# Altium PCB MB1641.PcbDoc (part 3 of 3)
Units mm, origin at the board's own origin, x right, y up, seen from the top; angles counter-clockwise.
Board outline 70 x 64.48 mm, 4 copper layers (Top Layer, GND, VCC, Bottom Layer), stack 1.502 mm thick; 161 components, 126 nets, 622 pads, 1092 vias.
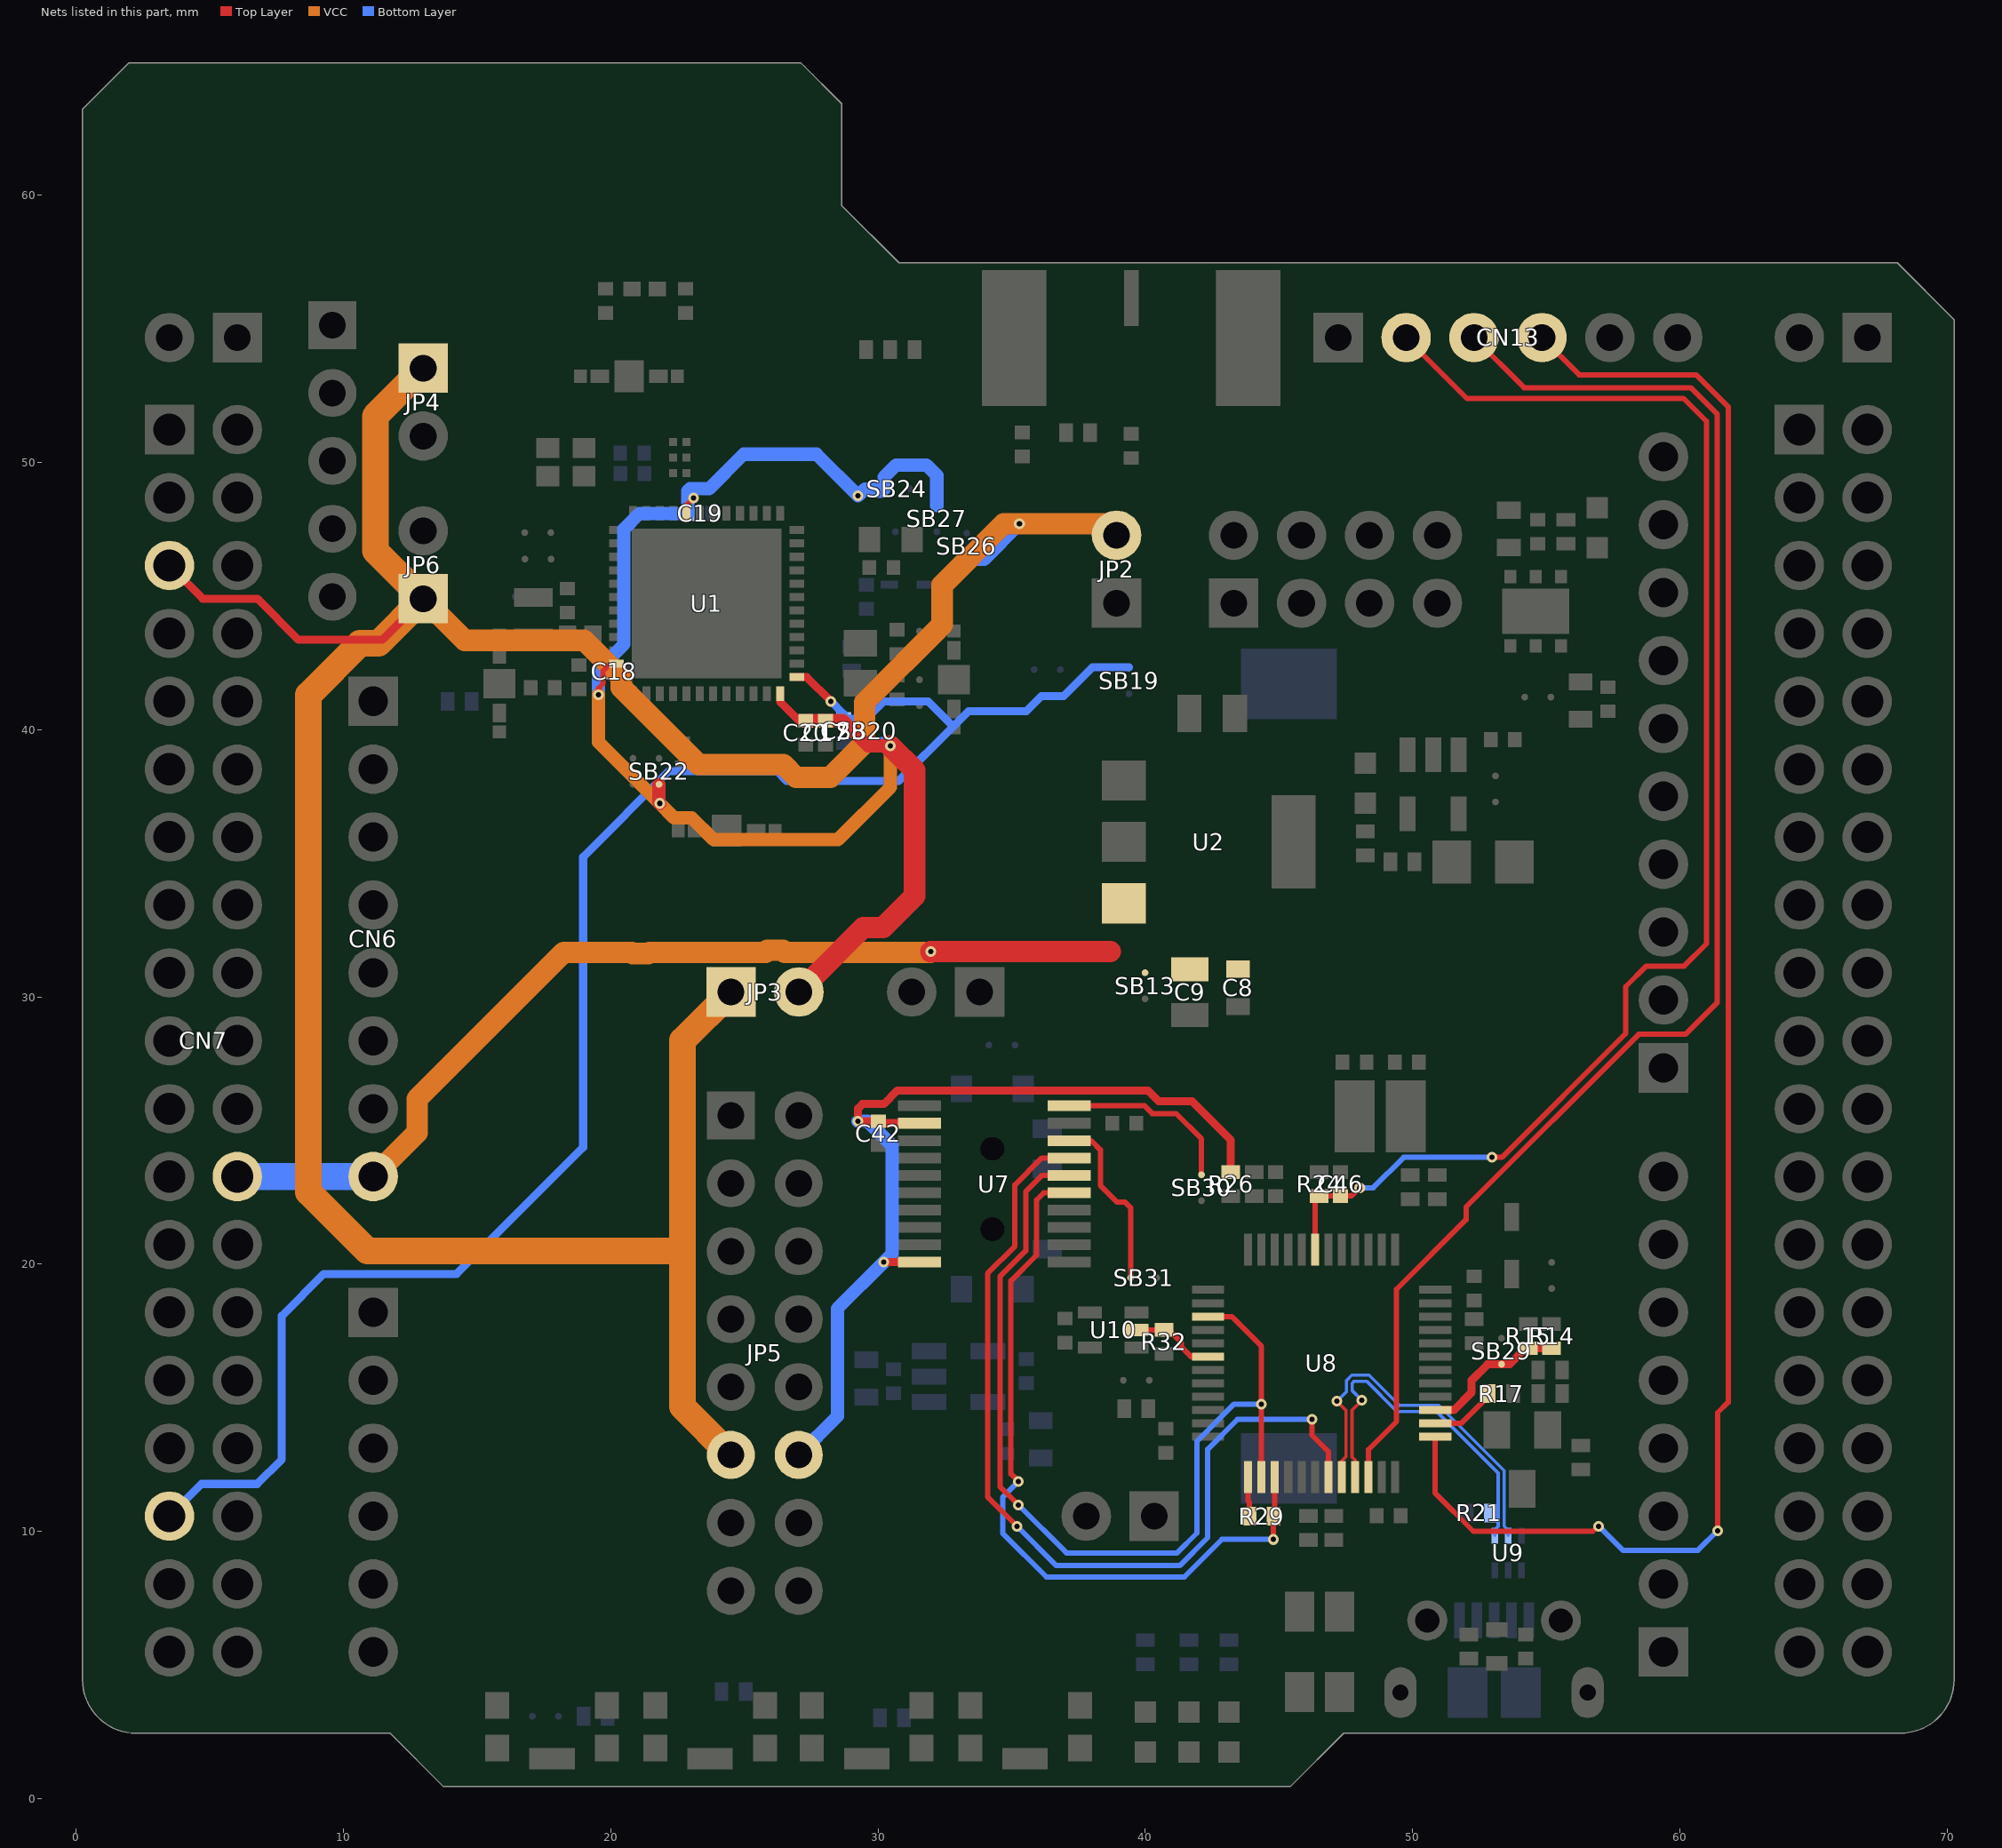
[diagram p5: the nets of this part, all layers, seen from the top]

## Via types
v1: diameter 0.4, hole 0.2, Top Layer to Bottom Layer, tented both sides, 1003 vias
v2: diameter 0.4/0.4/0.3/0.4 (per signal layer), hole 0.2, Top Layer to Bottom Layer, tented both sides, 89 vias

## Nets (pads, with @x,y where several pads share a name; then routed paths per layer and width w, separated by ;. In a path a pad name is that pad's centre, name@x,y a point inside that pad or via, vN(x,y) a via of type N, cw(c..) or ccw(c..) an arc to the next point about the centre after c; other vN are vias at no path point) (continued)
PWR_EXT: R14.2 R15.1 SB29.2 U8.39 | length 5.6
  Top Layer w0.3: U8.39@50.845,14.544 51.54,14.544 52.2,15.204 52.2,15.66 52.799,16.259 SB29.2@53.323,16.259 53.622,16.259 54.222,16.859 R15.1@54.326,16.859 R14.2@55.198,16.859
STLK_RST: C46.2 CN13.2 R24.1 U8.7 | length 53.6
  Top Layer w0.2: U8.7@46.345,20.544 46.345,22.395 R24.1@46.5,22.55 C46.2@47.3,22.55 47.708,22.55 v1(48.02,22.862) ; CN13.2@49.754,54.664 52.031,52.387 60.134,52.387 60.99,51.53 60.99,31.99 60.155,31.155 58.735,31.155 57.965,30.385 57.965,28.628 53.337,24 v1(52.96,24)
  Bottom Layer w0.2: v1(48.02,22.862) 48.521,22.862 49.659,24 v1(52.96,24)
STLK_RX: SB31.1 U7.18 | length 6.7
  Top Layer w0.2: U7.18@37.152,24.625 37.975,24.625 38.319,24.281 38.319,22.947 38.933,22.333 39.233,22.333 39.45,22.116 SB31.1@39.45,19.494
STLK_SWCLK: CN13.4 U8.37 | length 64.2
  Top Layer w0.2: U8.37@50.845,13.544 50.845,11.433 52.265,10.013 56.735,10.013 v1@56.924,10.201 ; CN13.4@54.834,54.664 56.224,53.274 60.601,53.274 61.797,52.078 61.797,14.839 61.406,14.448 v1(61.406,10.034)
  Bottom Layer w0.2: v1(56.957,10.201) 57.858,9.3 60.672,9.3 v1(61.406,10.034)
STLK_SWDIO: CN13.3 U8.34 | length 56.5
  Top Layer w0.2: U8.34@48.345,12.044 48.345,13.064 49.392,14.111 49.392,19.067 51.994,21.669 51.994,22.144 58.45,28.6 60.2,28.6 61.394,29.794 61.394,51.796 60.4,52.79 54.168,52.79 CN13.3@52.294,54.664
STLK_TX: SB30.1 U7.20 | length 6.8
  Top Layer w0.2: U7.20@37.152,25.925 39.975,25.925 40.26,25.64 41.15,25.64 42.1,24.69 SB30.1@42.1,23.35
T_NRST: R32.1 U8.18 U10.2 | length 3.2
  Top Layer w0.2: U10.2@39.675,17.54 40.69,17.54 R32.1@40.7,17.55 40.87,17.55 41.34,17.08 41.34,16.91 41.706,16.544 U8.18@42.345,16.544
T_SWCLK: U7.16 U8.15 U8.26 | length 35.8
  Top Layer w0.2: v1@35.254,10.995 v1(35.249,11) 34.567,11.682 34.567,19.544 35.527,20.504 35.527,22.719 36.133,23.325 U7.16@37.152,23.325 ; U8.15@42.345,18.044 43.229,18.044 44.345,16.929 v1(44.345,14.767) U8.26@44.345,12.044
  Bottom Layer w0.2: v1(35.249,11) 37.049,9.2 41.186,9.2 41.931,9.945 41.931,13.378 43.32,14.767 v1(44.345,14.767)
T_SWDIO: R29.1 U7.15 U8.27 | length 28.3
  Top Layer w0.2: v1(35.254,11.875) 34.97,12.159 34.97,19.377 35.93,20.337 35.93,22.4 36.205,22.675 U7.15@37.152,22.675 ; v1(44.795,9.705) R29.1@44.795,10.576 44.845,10.626 U8.27@44.845,12.044
  Bottom Layer w0.2: v1(35.254,11.875) 34.673,11.294 34.673,9.927 36.3,8.3 41.457,8.3 42.862,9.705 v1(44.795,9.705)
T_SWDIO_IN: R29.2 U8.25 | length 1.5
  Top Layer w0.2: U8.25@43.845,12.044 43.845,11.155 43.895,11.105 R29.2@43.895,10.576
T_SWO: U7.17 U8.31 | length 34.3
  Top Layer w0.2: v1(35.2,10.2) 34.1,11.3 34.1,19.654 35.119,20.673 35.119,22.965 36.129,23.975 U7.17@37.152,23.975 ; v1(46.227,14.2) 46.227,13.618 46.845,13 U8.31@46.845,12.044
  Bottom Layer w0.2: v1(35.2,10.2) 36.67,8.73 41.286,8.73 42.334,9.778 42.334,13.083 43.451,14.2 v1(46.227,14.2)
T_VDD: C42.2 JP5.12 R26.1 U7.2 U7.10 | length 35
  Top Layer w0.3: v1(30.212,20.075) U7.10@31.552,20.075 ; U7.2@31.552,25.275 30.087,25.275 C42.2@30.012,25.35 v1(29.256,25.35) 29.256,25.823 29.425,25.992 30.219,25.992 30.726,26.5 40.1,26.5 40.5,26.1 41.74,26.1 43.2,24.64 R26.1@43.2,23.45
  Bottom Layer w0.5: JP5.12@27.037,12.867 28.48,14.31 28.48,18.342 v1(30.212,20.075) 30.528,20.39 30.528,24.434 29.612,25.35 v1(29.256,25.35)
USB_RENUMn: R17.1 U8.38 | length 2.5
  Top Layer w0.2: U8.38@50.845,14.044 51.804,14.044 52.85,15.09 R17.1@52.85,15.159
USBSTLK_N: U8.32 U9.2 | length 13.9
  Top Layer w0.12: v1(47.165,14.873) 47.5,14.539 47.5,12.8 47.345,12.645 U8.32@47.345,12.044
  Bottom Layer w0.12: v1(47.165,14.873) 47.522,15.23 47.522,15.648 47.721,15.848 48.367,15.848 49.496,14.718 50.981,14.718 53.418,12.281 53.418,10.203 53.574,10.047 U9.2@53.574,9.85
USBSTLK_P: R21.1 U8.33 U9.1 | length 13.2
  Top Layer w0.12: U8.33@47.845,12.044 47.845,12.675 47.731,12.789 47.731,14.54 v1(48.1,14.909)
  Bottom Layer w0.12: v1(48.1,14.909) 47.744,15.265 47.744,15.556 47.813,15.626 48.275,15.626 49.404,14.496 50.889,14.496 53.196,12.189 53.196,10.194 53.074,10.072 U9.1@53.074,9.85
VBAT: C28.1 CN7.33 SB19.2 SB20.2 U1.1 | length 66.1
  Top Layer w0.3: U1.1@26.964,41.962 27.338,41.962 v1(28.239,41.061)
  Bottom Layer w0.3: CN7.33@3.5,10.58 4.702,11.782 6.782,11.782 7.7,12.7 7.7,18.069 9.271,19.64 14.24,19.64 18.974,24.374 18.974,35.233 22.188,38.447 26.211,38.447 26.58,38.078 30.777,38.078 32.817,40.118 ; v1(28.239,41.061) 28.718,40.582 C28.1@28.718,40.403 29.562,40.403 SB20.2@29.6,40.441 30.22,41.061 31.875,41.061 32.817,40.118 ; SB19.2@39.39,42.328 38.02,42.328 36.946,41.253 36.117,41.253 35.546,40.682 33.381,40.682 32.817,40.118
VDD: CN7.5 JP2.2 JP3.1 JP4.1 JP5.11 JP6.1 SB26.2 | length 116.8
  Top Layer w0.3: CN7.5@3.5,46.14 4.746,44.894 6.792,44.894 8.324,43.362 11.46,43.362 JP6.1@12.992,44.894
  VCC w0.8: JP6.1@12.992,44.894 14.548,43.339 19.011,43.339 20.387,41.963 20.387,41.907 20.403,41.891 20.403,41.575 23.278,38.7 26.457,38.7 26.943,38.214 28.214,38.214 29.5,39.5 29.5,41.017 32.4,43.917 32.4,45.4 34.7,47.7 v1(35.292,47.7) 38.495,47.7 JP2.2@38.925,47.27
  VCC w1: JP4.1@12.992,53.519 11.2,51.727 11.2,46.687 JP6.1@12.992,44.894 11.327,43.229 10.629,43.229 8.7,41.3 8.7,22.7 10.9,20.5 22.687,20.5 ; JP5.11@24.497,12.867 22.687,14.677 22.687,20.5 ; JP3.1@24.503,30.183 22.687,28.367 22.687,20.5
  Bottom Layer w0.5: SB26.2@33.32,46.375 33.967,46.375 v1(35.292,47.7)
VDD_MCU: C17.2 C18.2 C19.2 C20.2 JP3.2 SB20.1 SB22.1 SB24.1 SB27.2 U1.20 U1.35 U1.48 | length 60.2
  Top Layer w0.2: v1(19.55,41.3) 19.55,41.546 19.713,41.709 19.713,42.195 19.98,42.462 U1.35@20.214,42.462 U1.35@20.195,42.443 ; U1.20@22.839,48.087 22.839,48.407 v1(23.099,48.666)
  Top Layer w0.3: U1.48@26.339,41.337 26.339,41.045 27.049,40.335 C20.2@27.3,40.335
  Top Layer w0.5: SB22.1@21.81,37.95 21.81,37.268 v1(21.839,37.239) ; C20.2@27.3,40.335 C17.2@28.042,40.335 28.688,40.335 29.639,39.384 v1(30.469,39.384)
  Top Layer w0.8: JP3.2@27.043,30.183 29.45,32.59 30.19,32.59 31.37,33.77 31.37,38.483 v1(30.469,39.384)
  VCC w0.5: v1@19.55,41.319 v1(19.55,41.3) 19.55,39.53 19.549,39.529 v1(21.839,37.239) 22.375,36.703 23.03,36.703 23.85,35.883 28.503,35.883 30.469,37.849 v1(30.469,39.384)
  Bottom Layer w0.5: v1@19.55,41.319 19.55,42.299 19.608,42.299 20.5,43.191 20.5,47.5 21.087,48.087 C19.2@22.889,48.087 22.889,48.933 22.963,49.008 23.683,49.008 24.975,50.3 27.7,50.3 v1(29.256,48.744) 29.512,49 29.893,49 29.98,48.913 30.138,48.913 SB24.1@30.225,49 30.225,49.445 30.68,49.9 31.807,49.9 32.2,49.507 SB27.2@32.2,48.375 ; SB20.1@29.682,39.384 SB20.1@29.6,39.466 30.387,39.466 v1(30.469,39.384)
VIN: C8.2 C9.1 CN6.8 CN7.24 SB13.2 U2.3 | length 36.9
  Top Layer w0.8: v1(31.97,31.69) 31.98,31.7 38.689,31.7
  VCC w0.8: CN6.8@11.12,23.28 12.76,24.92 12.76,26.18 18.251,31.671 20.786,31.671 20.833,31.624 21.413,31.624 21.46,31.671 25.79,31.671 25.86,31.741 26.44,31.741 26.51,31.671 v1@31.951,31.671
  Bottom Layer w1: CN7.24@6.04,23.28 CN6.8@11.12,23.28
pads on no net: B1.5 B2.5 B3.5 B4.5 CN6.1 CN7.1 CN7.2 CN7.3 CN7.4 CN7.9 CN7.11 CN7.17 CN7.21 CN7.22 CN7.23 CN7.26 CN7.29 CN7.31 CN7.35 CN7.37 CN10.1 CN10.2 CN10.4 CN10.6 CN10.10 CN10.16 CN10.18 CN10.22 CN10.24 CN10.26 CN10.28 CN10.34 CN10.36 CN10.38 CN13.5 SW5.NPTH1 SW5.NPTH2 U3.3 U3.5 U7.7 U7.8 U7.9 U8.4 U8.11 U8.14 U8.16 U8.17 U8.19 U8.22 U8.29 U8.40 U8.41 U8.42 U8.43 U8.45 U8.46 U9.4 U10.1

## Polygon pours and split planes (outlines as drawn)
GND on Top Layer "Top Layer-GND" (solid, remove dead copper, pour order 42): -0.442,57.548 1.658,57.548 70.937,57.548 75.758,52.727 75.858,52.627 75.858,9.707 75.858,3.807 69.058,-2.993 66.458,-5.593 33.958,-5.593 0.458,-5.593 -5.042,-0.093 -8.842,3.707 -8.842,37.501 -8.842,53.107 -4.442,57.507
GND on Top Layer "Top Layer-GND" (solid, remove dead copper, pour order 20): 45.512,57.494 45.512,57.46 45.512,51.409 45.512,50.895 44.162,49.545 43.895,49.278 37.432,49.278 31.864,49.278 30.075,51.067 25.009,51.067 24.69,51.067 23.551,49.928 23.551,49.15 23.154,48.753 23.154,47.333 21.274,47.333 21.242,48.698 20.662,49.278 20.751,49.367 20.751,50.956 20.751,52.442 18.94,54.253 18.662,54.532 18.662,56.653 18.662,57.172 18.984,57.494 37.056,57.494
VIN on Top Layer "Top Layer-VIN" (solid, remove dead copper, pour order 18): 39.364,34.251 40.225,34.251 42.549,34.251 44.1,32.7 44.1,31.2 44.1,30.821 43.9,30.621 43.879,30.6 42,30.6 38.214,30.6 37.9,30.914 37.7,31.114 37.7,31.4 37.7,32.636 39.119,34.251
3V3 on Top Layer "Top Layer-3V3" (solid, remove dead copper, pour order 24): 55.3,46.2 56.957,46.2 57.376,46.2 57.596,45.98 57.8,45.776 57.8,45.289 57.8,41.409 57.7,41.309 57.66,41.269 57.3,41.269 56.184,41.269 55.9,40.985 55.7,40.785 55.7,40.641 55.7,39.38 55.93,39.15 56.007,39.073 56.3,39.073 56.42,39.073 56.65,38.843 56.7,38.793 56.7,38.022 56.7,37.893 56.58,37.773 56.549,37.742 56.224,37.742 55.108,37.742 54.95,37.9 54.912,37.938 54.912,38.3 54.912,42.432 55.124,42.644 55.148,42.668 55.659,42.668 55.939,42.668 56.15,42.88 56.15,43.15 56.15,45.269 56.08,45.339 55.957,45.462 55.59,45.462 55.308,45.462 55.213,45.557 55.213,46.1 55.213,46.134 55.279,46.2
GND on Top Layer "Top Layer-GND" (solid, remove dead copper, pour order 16): 38.417,37.3 39.125,37.3 41.168,37.3 41.97,38.102 42.074,38.206 42.074,40.491 42.074,41.236 41.957,41.353 38.891,41.353 38.311,40.773 38.311,37.406
5V_INT on Top Layer "Top Layer-5V_INT" (solid, remove dead copper, pour order 14): 38.4,34.748 41.631,34.748 43.076,34.748 43.9,33.923 44.185,33.639 45.6,33.639 46.325,33.639 46.67,33.984 46.845,34.159 46.845,35.662 46.845,41.403 46.157,42.091 45.5,42.091 43.175,42.091 42.85,41.766 42.745,41.661 42.745,40.9 42.745,37.375 42.174,36.8 42.074,36.7 39.862,36.7 38.4,36.7 38.2,36.5 38.2,36.098 38.2,34.859 38.311,34.748
5V_USB_STLINK on Top Layer "Top Layer-5V_USB_STLINK" (solid, remove dead copper, pour order 12): 53.446,37.529 52.8,37.529 51.287,37.529 51.258,37.5 51.2,37.442 51.2,36.9 51.2,36.4 50.7,35.9 50.3,35.5 50.12,35.5 49.854,35.5 49.754,35.4 49.754,35.048 49.754,34.409 49.545,34.2 49,34.2 48.7,34.2 48.6,34.3 48.6,34.7 48.6,35.524 48.524,35.6 48.181,35.6 47.831,35.6 47.731,35.5 47.731,34.748 47.731,32.617 48.314,32.034 51.679,32.034 52.2,32.555 52.2,34.2 52.2,35.725 52.475,36 53.15,36 53.356,36 53.554,36.198 53.65,36.294 53.65,36.8 53.65,37.479 53.6,37.529
NetC12_2 on Top Layer "Top Layer-NetC12_2" (solid, remove dead copper, pour order 10): 51.4,38.343 51.409,38.334 52.193,38.334 52.468,38.334 52.654,38.148 52.7,38.102 52.7,37.954 52.746,37.9 53.096,37.9 53.5,37.9 53.6,38 53.622,38.022 53.622,38.442 53.622,38.682 53.4,38.904 53.3,39.004 53.3,39.629 53.3,41.9 53.133,42.068 51.676,42.076 51.4,41.8
5V on Top Layer "Top Layer-5V" (solid, remove dead copper, pour order 6): 53.97,43.316 53.97,42.947 53.97,42.87 53.8,42.7 53.52,42.42 52.524,42.42 52.3,42.644 52.3,43.854 52.3,46.946 52.624,47.27 52.654,47.3 54.402,47.3 56,47.3 56.1,47.2 56.15,47.15 56.15,46.962 56.15,46.72 56.03,46.6 55.93,46.5 55.213,46.5 54.3,46.5 54,46.2 53.925,46.125 53.925,45.73 53.925,45.557 53.868,45.5 53.83,45.462 53.671,45.462 53.321,45.462 53.259,45.4 53.182,45.324 53.182,44.4 53.182,43.517 53.259,43.441 53.3,43.4 53.671,43.4 53.935,43.4 53.944,43.391
ANT on Top Layer "Top Layer-ANT" (solid, pour order 0): 20.021,57.65 20.021,59.275 17.546,59.275 17.546,60 26.471,60 26.471,61.65 17.546,61.65 17.546,62.375 26.496,62.375 26.496,64.05 19.521,64.05 19.521,63.6 23.921,63.6 26.021,63.6 26.021,62.85 17.096,62.85 17.096,62.8 17.096,61.175 17.121,61.175 25.996,61.175 25.996,60.8 25.996,60.425 25.921,60.425 17.096,60.425 17.096,60.4 17.096,58.775 17.121,58.775 19.621,58.775 19.621,57.625 20.021,57.625
GND on Bottom Layer "Bottom Layer-GND" (solid, remove dead copper, pour order 44): 1.448,57.511 3.548,57.511 72.827,57.511 77.648,52.69 77.748,52.59 77.748,9.67 77.748,3.77 70.948,-3.03 68.348,-5.63 35.848,-5.63 2.348,-5.63 -3.152,-0.13 -6.952,3.67 -6.952,37.464 -6.952,53.07 -2.552,57.47
5V_USB_STLINK on Bottom Layer "Bottom Layer-5V_USB_STLINK" (solid, remove dead copper, pour order 40): 29.08,15.3 29.08,13.862 29.292,13.65 32.771,13.65 33.177,14.056 33.177,16.872 32.851,17.199 31.299,17.199 31.162,17.062 31.162,16.504 31.216,16.45 32.568,16.45 32.668,16.35 32.668,15.387 32.531,15.25 31.013,15.25 30.856,15.407 29.138,15.407 29.094,15.363
3V3_STLINK on Bottom Layer "Bottom Layer-3V3_STLINK" (solid, remove dead copper, pour order 2): 34.315,15.159 33.54,15.159 33.46,15.079 33.46,13.782 33.642,13.6 36.757,13.6 37,13.357 37,12.92 37.32,12.6 40.19,12.6 40.3,12.71 40.3,14.129 39.62,14.809 36.6,14.809 35.358,14.809 35.008,15.159
GND on VCC "VCC" (solid, remove dead copper, pour order 28): -0.2,57.541 1.9,57.541 71.179,57.541 76,52.72 76.1,52.62 76.1,9.7 76.1,3.8 69.3,-3 66.7,-5.6 34.2,-5.6 0.7,-5.6 -4.8,-0.1 -8.6,3.7 -8.6,37.494 -8.6,53.1 -4.2,57.5
GND on GND "GND" (solid, remove dead copper, pour order 38): -0.2,57.541 1.9,57.541 71.179,57.541 76,52.72 76.1,52.62 76.1,9.7 76.1,3.8 69.3,-3 66.7,-5.6 34.2,-5.6 0.7,-5.6 -4.8,-0.1 -8.6,3.7 -8.6,37.494 -8.6,53.1 -4.2,57.5

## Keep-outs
Top Layer:
  rectangle: 29.997,53.902 30.053,54.538
  rectangle: 30.887,53.924 30.925,54.563
  rectangle: 37.475,50.774 37.5,51.456
GND:
  lines w0.05: 22.151,49.767 22.504,49.767 22.504,47.806 22.154,47.806 22.151,49.767
Keep-Out Layer:
  lines w0.1: 0.25,57.46 0.25,4.46 ccw(c2.25,4.46) 2.25,2.46 11.75,2.46 13.751,0.459 45.423,0.459 47.424,2.46 68.25,2.46 ; 0.25,57.46 0.25,57.46 ; 0.25,57.46 0.25,63.21 1.976,64.936 27.122,64.936 28.646,63.412 28.646,59.602 30.788,57.46 68.126,57.46 70.25,55.336 70.25,4.46 cw(c68.25,4.46) 68.25,2.46 ; 68.25,2.46 68.25,2.46 ; 3.52,2.663 3.52,3.918 6.475,3.918 6.475,2.663 3.52,2.663
  lines w0.102: 13.731,0.444 ccw(c13.766,0.48) 13.777,0.43 ccw(c13.779,0.481) 13.779,0.43 ; 45.417,0.43 ccw(c45.451,0.467) 45.487,0.431
  lines w0.127: 0.25,4.46 ccw(c2.25,4.46) 2.25,2.46 ; 68.25,2.46 ccw(c68.25,4.46) 70.25,4.46

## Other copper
Top Layer:
  text "1" at 3.886,3.041 h0.51
GND:
  text "2" at 4.446,3.04 h0.51
VCC:
  text "3" at 5.146,3.03 h0.51
Bottom Layer:
  text "4" at 5.78,3.033 h0.51

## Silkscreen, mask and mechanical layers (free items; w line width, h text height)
Top Overlay:
  rectangle: 56.493,52.405 58.55,53.109
  lines w0.1: 0.546,57.541 30.62,57.541
  lines w0.12: 28.467,11.4 30.087,11.4 ; 29.952,31.483 29.952,32.767 ; 35.079,32.767 29.952,32.767 ; 35.112,31.483 35.112,32.767 ; 35.112,32.752 35.112,35.65 29.952,35.65 29.952,32.767 ; 36.48,9.3 36.48,6.824 41.64,6.824 41.64,9.3 ; 42.033,48.54 42.033,51.346 52.18,51.346 ; 42.033,50.365 52.188,50.365 ; 52.188,48.55 52.188,51.346
  lines w0.15: 51.994,13.19 51.994,15.603 52.693,16.302
  lines w0.2: 23.09,6.415 19.17,6.415 19.17,27.037 23.09,27.037 ; 28.467,6.415 30.087,6.415 30.087,14.81 ; 28.573,14.81 30.082,14.81
  text "J" at 2.17,57.49 h15.24
  text "STLINK (Reserved)" at 50,56.444 h0.6
  text "GND" at 63.88,56.444 h0.51
  text "GND" at 66.57,56.404 h0.51
  text "GND" at 2.957,56.21 h0.51
  text "GND" at 5.64,56.21 h0.51
  text "VDD" at 15.13,53.109 h0.51 r90
  text "SWDIO" at 51.289,52.5 h0.51
  text "SWCLK" at 53.941,52.5 h0.51
  text "Vref" at 59.5,52.5 h0.51
  text "GND" at 46.475,52.48 h0.51
  text "NRST" at 48.966,52.49 h0.51
  text "2" at 68.825,51.153 h0.51
  text "1" at 62.65,51.1 h0.51
  text "1" at 1.495,51.055 h0.51
  text "5V sources" at 44.7,50.57 h0.6
  text "D15" at 61.948,50.091 h1 r90
  text "VDDRF" at 15.24,49.93 h0.51 r90
  text "5V / VIN" at 46.729,48.724 h0.51 r90
  text "5V / EXT" at 44.27,48.689 h0.51 r90
  text "USB / STL" at 51.801,48.689 h0.51 r90
  text "USB / MCU" at 49.3,48.68 h0.51 r90
  text "3" at 1.384,48.562 h0.51
  text "4" at 68.825,48.512 h0.51
  text "3" at 62.624,48.354 h0.51
  text "D14" at 62,47.27 h1 r90
  text "VDD" at 37,46.9 h0.51 r90
  text "VDDSMPS" at 15.25,46.15 h0.51 r90
  text "6" at 68.825,45.895 h0.51
  text "5" at 1.384,45.87 h0.51
  text "5" at 62.624,45.661 h0.51
  text "VDD" at 15.221,44.17 h0.51 r90
  text "3V3" at 36.94,44.047 h0.51 r90
  text "8" at 68.825,43.381 h0.51
  text "7" at 1.384,43.228 h0.51
  text "AVDD" at 61.907,43.117 h1 r90
  text "7" at 62.624,43.02 h0.51
  text "8" at 7.569,42.562 h0.51
  text "GND" at 57.759,42.324 h1 r90
  text "10" at 68.825,40.866 h0.51
  text "9" at 1.409,40.841 h0.51
  text "10" at 7.598,40.669 h0.51
  text "9" at 62.648,40.632 h0.51
  text "D13" at 55.566,38.42 h1
  text "12" at 68.825,38.326 h0.51
  text "11" at 1.23,38.25 h0.51
  text "12" at 7.655,38.144 h0.51
  text "11" at 62.469,38.041 h0.51
  text "D12" at 55.623,36.77 h1
  text "IOREF" at 13.918,36.4 h1 r90
  text "13" at 1.012,35.71 h0.51
  text "14" at 68.825,35.71 h0.51
  text "14" at 7.54,35.649 h0.51
  text "13" at 62.251,35.501 h0.51
  text "NRST" at 12.8,34.77 h1
  text "D11" at 55.82,34.64 h1
  text "RF Part" at 24.356,34.621 h1
  text "15" at 1.012,33.246 h0.51
  text "16" at 68.825,33.17 h0.51
  text "16" at 7.54,33.153 h0.51
  text "15" at 62.251,33.038 h0.51
  text "3V3" at 12.83,32.85 h1
  text "Ext Battery" at 30.597,32.85 h0.75
  text "D10" at 55.623,32.106 h1
  text "-" at 30.62,31.74 h1
  text "+" at 33.351,31.72 h1
  text "18" at 68.825,30.655 h0.51
  text "17" at 1.012,30.605 h0.51
  text "18" at 7.511,30.515 h0.51
  text "17" at 62.251,30.396 h0.51
  text "5V" at 12.91,30.21 h1
  text "D9" at 55.98,29.327 h1
  text "K" at 15.316,28.702 h13
  text "20" at 68.825,28.369 h0.51
  text "19" at 1.036,28.166 h0.51
  text "20" at 7.569,28.105 h0.51
  text "VDD" at 23.012,27.963 h0.51
  text "19" at 62.275,27.958 h0.51
  text "VDD_MCU" at 25.54,27.926 h0.51
  text "GND" at 12.772,27.8 h1
  text "D8" at 56.08,26.788 h1
  text "22" at 68.825,25.728 h0.51
  text "21" at 1.15,25.626 h0.51
  text "21" at 62.125,25.624 h0.51
  text "22" at 7.615,25.613 h0.51
  text "GND" at 12.8,25.35 h1
  text "GND" at 20.792,25.335 h0.75
  text "24" at 68.825,23.061 h0.51
  text "23" at 0.932,22.985 h0.51
  text "23" at 61.907,22.982 h0.51
  text "24" at 7.626,22.913 h0.51
  text "D7" at 56.375,22.847 h1
  text "NRST" at 20.219,22.759 h0.75
  text "VIN" at 12.872,22.4 h1
  text "25" at 0.932,20.546 h0.51
  text "25" at 61.907,20.544 h0.51
  text "26" at 68.825,20.445 h0.51
  text "D6" at 56.347,20.337 h1
  text "26" at 7.626,20.303 h0.51
  text "SWDIO" at 19.837,20.277 h0.75
  text "27" at 0.932,18.108 h0.51
  text "27" at 61.907,18.105 h0.51
  text "28" at 68.825,18.057 h0.51
  text "28" at 7.655,17.836 h0.51
  text "SWCLK" at 19.456,17.639 h0.75
  text "D5" at 56.3,17.569 h1
  text "A0" at 12.807,17.48 h1
  text "30" at 68.825,15.492 h0.51
  text "30" at 7.598,15.456 h0.51
  text "29" at 0.956,15.39 h0.51
  text "29" at 61.932,15.387 h0.51
  text "D4" at 56.347,15.363 h1
  text "SWO" at 20.537,15.22 h0.75
  text "A1" at 12.888,14.976 h1
  text "D3" at 56.3,13.8 h1
  text "32" at 68.825,12.926 h0.51
  text "31" at 1.15,12.875 h0.51
  text "31" at 62.125,12.873 h0.51
  text "32" at 7.626,12.817 h0.51
  text "A2" at 12.868,12.581 h1
  text "VDD / MCU" at 20.41,11.88 h0.75
  text "T_VDD" at 29.579,11.6 h0.7 r90
  text "34" at 68.825,10.386 h0.51
  text "33" at 0.932,10.361 h0.51
  text "33" at 61.907,10.358 h0.51
  text "34" at 7.626,10.321 h0.51
  text "D2" at 56.347,10.201 h1
  text "MB1641C" at 18.161,10.16 h2.5 r90
  text "A3" at 12.807,9.969 h1
  text "TX" at 21.428,9.971 h0.75
  text "RX" at 29.748,9.398 h0.75 r90
  text "L" at 30.85,8.88 h7.62
  text "TX" at 37.2,8.24 h0.75
  text "RX" at 39.8,8.24 h0.75
  text "36" at 68.825,7.872 h0.51
  text "35" at 0.932,7.745 h0.51
  text "35" at 61.907,7.742 h0.51
  text "36" at 7.655,7.711 h0.51
  text "D1" at 56.545,7.5 h1
  text "A4" at 12.807,7.465 h1
  text "RX" at 21.46,7.394 h0.75
  text "STLINK" at 37.6,7.1 h0.75
  text "TX" at 29.748,6.866 h0.75 r90
  text "Reset" at 32.7,5.97 h1
  text "COM" at 44.75,5.63 h0.75 r90
  text "38" at 68.825,5.205 h0.51
  text "37" at 0.932,5.179 h0.51
  text "D0" at 56.357,5.15 h1
  text "38" at 7.583,5.083 h0.51
  text "A5" at 12.807,4.961 h1
  text "37" at 62.14,4.1 h0.51
  text "TOP SILKSCREEN" at -0.752,-18.74 h1.52
Bottom Overlay:
  lines w0.1: 7.5,51.79 7.5,55.39 8.55,55.39 ; 7.51,46.66 7.51,48.35 ; 7.51,49.1 7.51,50.92 ; 7.531,44.01 7.531,45.81 ; 7.73,43.3 11.71,43.3 11.71,55.55 ; 29.743,24.615 29.743,24.557 29.753,24.547 29.806,24.547 29.855,24.498 29.723,24.498 29.679,24.542 29.679,24.539 29.592,24.452 29.93,24.452 29.989,24.393 29.528,24.393 29.472,24.337 30.05,24.337 30.108,24.279 29.426,24.279 29.367,24.22 30.133,24.22 30.208,24.145 29.265,24.145 29.187,24.067 30.311,24.067 30.406,23.972 29.094,23.972 29.166,23.9 29.168,23.9 ; 29.757,20.973 29.757,21.032 29.747,21.042 29.694,21.042 29.645,21.091 29.776,21.091 29.82,21.047 29.82,21.049 29.908,21.137 29.57,21.137 29.511,21.195 29.972,21.195 30.027,21.251 29.45,21.251 29.391,21.31 30.074,21.31 30.133,21.368 29.367,21.368 29.292,21.444 30.235,21.444 30.313,21.522 29.189,21.522 29.094,21.617 30.405,21.617 30.334,21.688 30.332,21.688 ; 32.253,26.56 28.371,26.56 28.371,19.01 32.35,19.01 ; 29.168,23.9 30.527,23.9 29.75,24.676 28.974,23.9 29.168,23.9 ; 30.332,21.688 28.973,21.688 29.75,20.912 30.526,21.688 30.332,21.688
  text "GND" at 65.066,55.928 h0.51
  text "GND" at 67.581,55.776 h0.51
  text "AT0" at 10.84,54.01 h0.6 r270
  text "AT1" at 10.78,51.92 h0.6 r270
  text "2" at 68.857,51.179 h0.51
  text "2" at 7.5,51.13 h0.51
  text "1" at 1.845,50.975 h0.51
  text "1" at 62.897,50.848 h0.51
  text "AT2" at 10.8,49.29 h0.6 r270
  text "4" at 68.881,48.537 h0.51
  text "4" at 7.531,48.48 h0.51
  text "3" at 1.963,48.435 h0.51
  text "3" at 62.897,48.308 h0.51
  text "AT3" at 10.82,46.8 h0.6 r270
  text "E" at 57.27,46.129 h7.62
  text "6" at 7.5,46.01 h0.51
  text "6" at 68.833,45.921 h0.51
  text "5" at 1.963,45.895 h0.51
  text "5" at 62.897,45.768 h0.51
  text "GND" at 10.8,44.28 h0.6 r270
  text "Analog Test Pin (Reserved)" at 7.872,43.9 h0.6 r270
  text "8" at 68.857,43.406 h0.51
  text "7" at 1.963,43.355 h0.51
  text "8" at 7.61,43.32 h0.51
  text "7" at 62.897,43.228 h0.51
  text "10" at 69.229,40.892 h0.51
  text "9" at 1.963,40.815 h0.51
  text "10" at 8.193,40.739 h0.51
  text "9" at 62.897,40.688 h0.51
  text "12" at 69.229,38.352 h0.51
  text "G" at 58.04,38.332 h11
  text "11" at 1.963,38.275 h0.51
  text "12" at 8.193,38.199 h0.51
  text "11" at 62.897,38.148 h0.51
  text "C" at 21.62,35.95 h7.62
  text "13" at 1.963,35.735 h0.51
  text "14" at 69.253,35.735 h0.51
  text "13" at 62.897,35.608 h0.51
  text "14" at 8.217,35.583 h0.51
  text "15" at 1.963,33.195 h0.51
  text "16" at 69.205,33.195 h0.51
  text "15" at 62.897,33.068 h0.51
  text "16" at 8.169,33.043 h0.51
  text "I" at 25.95,32.707 h7.62
  text "H" at 21.46,31.93 h7.62
  text "CR2032" at 35.771,31.412 h0.9 r270
  text "18" at 69.229,30.681 h0.51
  text "17" at 1.963,30.655 h0.51
  text "18" at 8.193,30.528 h0.51
  text "17" at 62.897,30.528 h0.51
  text "20" at 69.309,28.395 h0.51
  text "20" at 8.273,28.242 h0.51
  text "19" at 1.963,28.115 h0.51
  text "19" at 62.897,27.988 h0.51
  text "22" at 69.309,25.753 h0.51
  text "22" at 8.273,25.601 h0.51
  text "21" at 1.963,25.575 h0.51
  text "21" at 62.897,25.448 h0.51
  text "Bat" at 32.131,24.948 h1
  text "24" at 69.333,23.086 h0.51
  text "23" at 1.963,23.035 h0.51
  text "24" at 8.297,22.934 h0.51
  text "23" at 62.897,22.908 h0.51
  text "25" at 1.963,20.495 h0.51
  text "26" at 69.285,20.47 h0.51
  text "25" at 62.897,20.368 h0.51
  text "26" at 8.249,20.318 h0.51
  text "ExtS" at 32.098,19.54 h1
  text "28" at 69.309,18.082 h0.51
  text "27" at 1.963,17.955 h0.51
  text "28" at 8.273,17.93 h0.51
  text "27" at 62.897,17.828 h0.51
  text "30" at 69.309,15.517 h0.51
  text "29" at 1.963,15.415 h0.51
  text "30" at 8.273,15.365 h0.51
  text "29" at 62.897,15.288 h0.51
  text "32" at 69.309,12.952 h0.51
  text "31" at 1.963,12.875 h0.51
  text "32" at 8.273,12.799 h0.51
  text "31" at 62.897,12.748 h0.51
  text "L" at 57.074,11.963 h7.62
  text "34" at 69.333,10.412 h0.51
  text "33" at 1.963,10.335 h0.51
  text "34" at 8.297,10.259 h0.51
  text "33" at 62.897,10.208 h0.51
  text "36" at 69.285,7.897 h0.51
  text "35" at 1.963,7.795 h0.51
  text "36" at 8.249,7.745 h0.51
  text "35" at 62.897,7.668 h0.51
  text "37" at 1.963,5.255 h0.51
  text "38" at 69.309,5.23 h0.51
  text "37" at 62.897,5.128 h0.51
  text "38" at 8.273,5.078 h0.51
  text "ST-LINK" at 47.479,2.777 h1 r270
  text "BOTTOM SILKSCREEN" at -0.433,-18.674 h1.52
Top Paste:
  text "TOP SOLDER PASTE" at -0.752,-18.74 h1.52
Bottom Paste:
  text "BOTTOM SOLDER PASTE" at -0.179,-18.7 h1.52
Top Solder:
  text "TOP SOLDER MASK" at -0.752,-18.74 h1.52
Bottom Solder:
  text "BOTTOM SOLDER MASK" at -0.357,-18.7 h1.52
M1-Board Shape:
  lines w0.1: 0.25,4.46 0.25,57.46 0.25,63.21 1.976,64.936 27.122,64.936 28.646,63.412 28.646,59.602 30.788,57.46 32.964,57.46 68.126,57.46 70.25,55.336 70.25,4.46 ; 2.25,2.46 11.62,2.46 11.75,2.46 13.751,0.459 45.423,0.459 47.424,2.46 68.25,2.46
  lines w0.127: 0.25,4.46 ccw(c2.25,4.46) 2.25,2.46 ; 68.25,2.46 ccw(c68.25,4.46) 70.25,4.46
M14-Top Assembly:
  lines w0.1: 10.706,56.263 10.721,56.248 ; 23.157,6.344 23.157,26.917 28.407,26.917 28.407,6.344 23.157,6.344
Drill Drawing:
  drawing of 634 lines, arcs and shapes, not listed
  text "6" at -48.561,264.932 h3.3
  text "6" at -48.561,264.932 h3.3
  text "5" at 40.339,264.932 h3.3
  text "5" at 40.339,264.932 h3.3
  text "4" at 129.239,264.932 h3.3
  text "4" at 129.239,264.932 h3.3
  text "3" at 218.139,264.932 h3.3
  text "3" at 218.139,264.932 h3.3
  text "2" at 307.039,264.932 h3.3
  text "2" at 307.039,264.932 h3.3
  text "1" at 395.939,264.932 h3.3
  text "1" at 395.939,264.932 h3.3
  text "Symbol" at 227.222,217.166 h2.16
  text "Count" at 235.683,217.166 h2.16
  text "Hole Size" at 245.25,217.166 h2.16
  text "Plated" at 260.8,217.166 h2.16
  text "Hole Type" at 268.229,217.166 h2.16
  text "Drill Layer Pair" at 279.043,217.166 h2.16
  text "Via/Pad" at 299.542,217.166 h2.16
  text "Pad Shape" at 308.404,217.166 h2.16
  text "Template" at 319.98,217.166 h2.16
  text "Description" at 345.977,217.166 h2.16
  text "Hole Tolerance (+)" at 357.603,217.166 h2.16
  text "Hole Tolerance (-)" at 375.682,217.166 h2.16
  text "Hole Length" at 393.275,217.166 h2.16
  text "Routed Path Length" at 408.717,217.166 h2.16
  text "2" at 235.683,213.437 h1.8
  text "0,60mm (23,62mil)" at 245.25,213.437 h1.8
  text "PTH" at 260.8,213.437 h1.8
  text "Slot" at 268.229,213.437 h1.8
  text "Top Layer - Bottom Layer" at 279.043,213.437 h1.8
  text "Pad" at 299.542,213.437 h1.8
  text "Rounded" at 308.404,213.437 h1.8
  text "r190_120h60_130r100m195_125" at 319.98,213.437 h1.8
  text "1,30mm (51,18mil)" at 393.275,213.437 h1.8
  text "0,70mm (27,56mil)" at 408.717,213.437 h1.8
  text "2" at 235.683,209.709 h1.8
  text "0,90mm (35,43mil)" at 245.25,209.709 h1.8
  text "NPTH" at 260.8,209.709 h1.8
  text "Round" at 268.229,209.709 h1.8
  text "Top Layer - Bottom Layer" at 279.043,209.709 h1.8
  text "Pad" at 299.542,209.709 h1.8
  text "Rounded" at 308.404,209.709 h1.8
  text "c90hn90m95" at 319.98,209.709 h1.8
  text "-" at 393.275,209.709 h1.8
  text "-" at 408.717,209.709 h1.8
  text "D" at -99.361,206.512 h3.3
  text "D" at -99.361,206.512 h3.3
  text "D" at 441.659,206.512 h3.3
  text "D" at 441.659,206.512 h3.3
  text "2" at 235.683,205.981 h1.8
  text "0,90mm (35,43mil)" at 245.25,205.981 h1.8
  text "PTH" at 260.8,205.981 h1.8
  text "Round" at 268.229,205.981 h1.8
  text "Top Layer - Bottom Layer" at 279.043,205.981 h1.8
  text "Pad" at 299.542,205.981 h1.8
  text "Rounded" at 308.404,205.981 h1.8
  text "c150h90m155" at 319.98,205.981 h1.8
  text "-" at 393.275,205.981 h1.8
  text "-" at 408.717,205.981 h1.8
  text "32" at 235.683,202.253 h1.8
  text "1,10mm (43,31mil)" at 245.25,202.253 h1.8
  text "PTH" at 260.8,202.253 h1.8
  text "Round" at 268.229,202.253 h1.8
  text "Top Layer - Bottom Layer" at 279.043,202.253 h1.8
  text "Pad" at 299.542,202.253 h1.8
  text "Rounded" at 308.404,202.253 h1.8
  text "(Mixed)" at 319.98,202.253 h1.8
  text "-" at 393.275,202.253 h1.8
  text "-" at 408.717,202.253 h1.8
  text "51" at 235.683,198.525 h1.8
  text "1,00mm (39,37mil)" at 245.25,198.525 h1.8
  text "PTH" at 260.8,198.525 h1.8
  text "Round" at 268.229,198.525 h1.8
  text "Top Layer - Bottom Layer" at 279.043,198.525 h1.8
  text "Pad" at 299.542,198.525 h1.8
  text "(Mixed)" at 308.404,198.525 h1.8
  text "(Mixed)" at 319.98,198.525 h1.8
  text "-" at 393.275,198.525 h1.8
  text "-" at 408.717,198.525 h1.8
  text "76" at 235.683,194.796 h1.8
  text "1,20mm (47,24mil)" at 245.25,194.796 h1.8
  text "PTH" at 260.8,194.796 h1.8
  text "Round" at 268.229,194.796 h1.8
  text "Top Layer - Bottom Layer" at 279.043,194.796 h1.8
  text "Pad" at 299.542,194.796 h1.8
  text "Rounded" at 308.404,194.796 h1.8
  text "(Mixed)" at 319.98,194.796 h1.8
  text "-" at 393.275,194.796 h1.8
  text "-" at 408.717,194.796 h1.8
  text "1092" at 235.683,191.068 h1.8
  text "0,20mm (7,87mil)" at 245.25,191.068 h1.8
  text "PTH" at 260.8,191.068 h1.8
  text "Round" at 268.229,191.068 h1.8
  text "Top Layer - Bottom Layer" at 279.043,191.068 h1.8
  text "Via" at 299.542,191.068 h1.8
  text "Rounded" at 308.404,191.068 h1.8
  text "(Mixed)" at 319.98,191.068 h1.8
  text "-" at 393.275,191.068 h1.8
  text "-" at 408.717,191.068 h1.8
  text "1257 Total" at 235.683,187.34 h1.8
  text "Slot definitions :" at 227.222,184.73 h1.8
  text "Routed Path Length" at 239.507,184.73 h1.8
  text "= Calculated from tool start centre position to tool end centre position." at 254.727,184.73 h1.8
  text "Hole Length" at 239.507,183.239 h1.8
  text "= Routed Path Length + Tool Size = Slot length as defined in the PCB layout" at 249.077,183.239 h1.8
  text "Layer" at 226.373,175.331 h1.52
  text "Name" at 236.785,175.331 h1.52
  text "Material" at 260.4,175.331 h1.52
  text "Thickness" at 282.238,175.331 h1.52
  text "Constant" at 298.744,175.331 h1.52
  text "Board Layer Stack" at 313.219,175.331 h1.52
  text "Top Overlay" at 236.785,172.283 h1.52
  text "Top Solder" at 236.785,169.235 h1.52
  text "Solder Resist" at 260.4,169.235 h1.52
  text "0,015mm" at 282.238,169.235 h1.52
  text "3,5" at 298.744,169.235 h1.52
  text "1" at 226.373,166.187 h1.52
  text "Top Layer" at 236.785,166.187 h1.52
  text "Copper" at 260.4,166.187 h1.52
  text "0,012mm" at 282.238,166.187 h1.52
  text "Dielectric 1" at 236.785,163.139 h1.52
  text "FR-4" at 260.4,163.139 h1.52
  text "0,506mm" at 282.238,163.139 h1.52
  text "4,2" at 298.744,163.139 h1.52
  text "2" at 226.373,160.091 h1.52
  text "GND" at 236.785,160.091 h1.52
  text "Copper" at 260.4,160.091 h1.52
  text "0,018mm" at 282.238,160.091 h1.52
  text "Dielectric3" at 236.785,157.043 h1.52
  text "FR-4" at 260.4,157.043 h1.52
  text "0,430mm" at 282.238,157.043 h1.52
  text "4,2" at 298.744,157.043 h1.52
  text "3" at 226.373,153.995 h1.52
  text "VCC" at 236.785,153.995 h1.52
  text "Copper" at 260.4,153.995 h1.52
  text "0,018mm" at 282.238,153.995 h1.52
  text "Dielectric5" at 236.785,150.947 h1.52
  text "FR-4" at 260.4,150.947 h1.52
  text "0,506mm" at 282.238,150.947 h1.52
  text "4,2" at 298.744,150.947 h1.52
  text "4" at 226.373,147.899 h1.52
  text "Bottom Layer" at 236.785,147.899 h1.52
  text "Copper" at 260.4,147.899 h1.52
  text "0,012mm" at 282.238,147.899 h1.52
  text "Bottom Solder" at 236.785,144.851 h1.52
  text "Solder Resist" at 260.4,144.851 h1.52
  text "0,015mm" at 282.238,144.851 h1.52
  text "3,5" at 298.744,144.851 h1.52
  text "Bottom Overlay" at 236.785,141.803 h1.52
  text "PCB SPECIFICATIONS:" at 225.186,126.022 h2.16
  text "PCB SPECIFICATIONS:" at 225.186,126.022 h2.16
  text "A. MATERIAL;" at 225.186,120.942 h2.16
  text "A. MATERIAL;" at 225.186,120.942 h2.16
  text "FR-4," at 269.636,120.942 h2.16
  text "FR-4," at 269.636,120.942 h2.16
  text "TG-170" at 293.766,120.942 h2.16
  text "TG-170" at 293.766,120.942 h2.16
  text "TG-150" at 312.816,120.942 h2.16
  text "TG-150" at 312.816,120.942 h2.16
  text "TG-140" at 334.406,120.942 h2.16
  text "TG-140" at 334.406,120.942 h2.16
  text "B. MATERIAL FAMILY;" at 225.186,115.862 h2.16
  text "B. MATERIAL FAMILY;" at 225.186,115.862 h2.16
  text "N/A." at 269.636,115.862 h2.16
  text "N/A." at 269.636,115.862 h2.16
  text "C. SOLDERMASK COLOR;" at 225.186,110.782 h2.16
  text "C. SOLDERMASK COLOR;" at 225.186,110.782 h2.16
  text "GREEN" at 273.446,110.782 h2.16
  text "GREEN" at 273.446,110.782 h2.16
  text "BLUE" at 292.496,110.782 h2.16
  text "BLUE" at 292.496,110.782 h2.16
  text "RED" at 314.086,110.782 h2.16
  text "RED" at 314.086,110.782 h2.16
  text "BLACK" at 335.676,110.782 h2.16
  text "BLACK" at 335.676,110.782 h2.16
  text "WHITE" at 358.155,110.731 h2.16
  text "WHITE" at 358.155,110.731 h2.16
  text "C" at -99.361,107.452 h3.3
  text "C" at -99.361,107.452 h3.3
  text "C" at 441.659,107.452 h3.3
  text "C" at 441.659,107.452 h3.3
  text "BLUE" at 335.727,105.905 h2.16
  text "BLUE" at 335.727,105.905 h2.16
  text "D. SILKSCREEN COLOR;" at 225.186,105.702 h2.16
  text "D. SILKSCREEN COLOR;" at 225.186,105.702 h2.16
  text "WHITE" at 273.446,105.702 h2.16
  text "WHITE" at 273.446,105.702 h2.16
  text "YELLOW" at 292.496,105.702 h2.16
  text "YELLOW" at 292.496,105.702 h2.16
  text "BLACK" at 314.086,105.702 h2.16
  text "BLACK" at 314.086,105.702 h2.16
  text "E. SURFACE FINISH;" at 225.186,100.622 h2.16
  text "E. SURFACE FINISH;" at 225.186,100.622 h2.16
  text "ENIG" at 273.446,100.622 h2.16
  text "ENIG" at 273.446,100.622 h2.16
  text "IMMERSION SILVER" at 292.496,100.622 h2.16
  text "IMMERSION SILVER" at 292.496,100.622 h2.16
  text "IMMERSION TIN" at 335.676,100.622 h2.16
  text "IMMERSION TIN" at 335.676,100.622 h2.16
  text "HASL" at 273.446,95.542 h2.16
  text "HASL" at 273.446,95.542 h2.16
  text "HASL(PB-FREE)" at 292.496,95.542 h2.16
  text "HASL(PB-FREE)" at 292.496,95.542 h2.16
  text "GOLDEN FINGER" at 335.676,95.542 h2.16
  text "GOLDEN FINGER" at 335.676,95.542 h2.16
  text "F. IMPEDANCE CONTROL;" at 225.186,90.462 h2.16
  text "F. IMPEDANCE CONTROL;" at 225.186,90.462 h2.16
  text "NO" at 273.446,90.462 h2.16
  text "NO" at 273.446,90.462 h2.16
  text "YES" at 292.496,90.462 h2.16
  text "YES" at 292.496,90.462 h2.16
  text "(SEE IMPEDANCE TABLE FOR DETAIL INFORMATION)" at 297.576,90.462 h2.16
  text "(SEE IMPEDANCE TABLE FOR DETAIL INFORMATION)" at 297.576,90.462 h2.16
  text "H. STACK-UP;" at 225.186,75.222 h2.16
  text "H. STACK-UP;" at 225.186,75.222 h2.16
  text "SEE LAYER STACK-UP SEQUENCE FOR OVERALL THICKNESS." at 262.016,75.222 h2.16
  text "SEE LAYER STACK-UP SEQUENCE FOR OVERALL THICKNESS." at 262.016,75.222 h2.16
  text "PCB REQUIREMENTS:" at 224.932,67.602 h2.16
  text "PCB REQUIREMENTS:" at 224.932,67.602 h2.16
  text "1. THIS BOARD WILL CONFORM TO:" at 223.662,62.522 h2.16
  text "1. THIS BOARD WILL CONFORM TO:" at 223.662,62.522 h2.16
  text "IPC-A-600. CURRENT REV., CLASS II" at 223.662,58.712 h2.16
  text "IPC-A-600. CURRENT REV., CLASS II" at 223.662,58.712 h2.16
  text "IPC-6012, CURRENT REV., CLASS II" at 223.662,54.902 h2.16
  text "IPC-6012, CURRENT REV., CLASS II" at 223.662,54.902 h2.16
  text "2. UNLESS OTHERWISE SPECIFIED ALL HOLE DIMENSIONS APPLY AFTER PLATING." at 223.662,49.568 h2.16
  text "2. UNLESS OTHERWISE SPECIFIED ALL HOLE DIMENSIONS APPLY AFTER PLATING." at 223.662,49.568 h2.16
  text "ALL HOLES SHALL BE LOCATED WITHIN .003\" DIAMETER OF TRUE POSITION." at 223.662,45.758 h2.16
  text "ALL HOLES SHALL BE LOCATED WITHIN .003\" DIAMETER OF TRUE POSITION." at 223.662,45.758 h2.16
  text "3. PLATED HOLE WALL THICKNESS SHALL NOT BE LESS THAN .001 INCH MINIMUM" at 223.662,40.678 h2.16
  text "3. PLATED HOLE WALL THICKNESS SHALL NOT BE LESS THAN .001 INCH MINIMUM" at 223.662,40.678 h2.16
  text "AVERAGE, WITH NO READING LESS THAN .0008 BY COROSS SECTION." at 228.234,37.122 h2.16
  text "AVERAGE, WITH NO READING LESS THAN .0008 BY COROSS SECTION." at 228.234,37.122 h2.16
  text "4. MATERIAL FR4 RATING 94V-0 MINIMUM EPOXY GLASS LAMINATE." at 223.662,31.788 h2.16
  text "4. MATERIAL FR4 RATING 94V-0 MINIMUM EPOXY GLASS LAMINATE." at 223.662,31.788 h2.16
  text "5. BOARD SHALL BE LPI SOLDER MASKED OVER BARE COPPER BOTH SIDES PER" at 223.662,27.216 h2.16
  text "5. BOARD SHALL BE LPI SOLDER MASKED OVER BARE COPPER BOTH SIDES PER" at 223.662,27.216 h2.16
  text "IPC-SM-840 CLASS II." at 223.662,23.406 h2.16
  text "IPC-SM-840 CLASS II." at 223.662,23.406 h2.16
  text "6. SILKSCREEN SHALL BE PERMANENT NON-CONDUCTIVE INK AND WITH NO OVERLAP" at 223.662,18.326 h2.16
  text "6. SILKSCREEN SHALL BE PERMANENT NON-CONDUCTIVE INK AND WITH NO OVERLAP" at 223.662,18.326 h2.16
  text "ON ANY COMPONENT PAD OR THROUGH HOLE." at 223.662,14.516 h2.16
  text "ON ANY COMPONENT PAD OR THROUGH HOLE." at 223.662,14.516 h2.16
  text "B" at -99.361,13.472 h3.3
  text "B" at -99.361,13.472 h3.3
  text "B" at 441.659,13.472 h3.3
  text "B" at 441.659,13.472 h3.3
  text "7. MFGR, TO LEGIBLY ETCH OR STAMP/SCREEN WITH PERMANENT NON-CONDUCTIVE INK" at 223.662,9.436 h2.16
  text "7. MFGR, TO LEGIBLY ETCH OR STAMP/SCREEN WITH PERMANENT NON-CONDUCTIVE INK" at 223.662,9.436 h2.16
  text "D. MFGR. LOGO" at 270.652,6.134 h2.16
  text "D. MFGR. LOGO" at 270.652,6.134 h2.16
  text "A. U.L. CODE" at 231.028,5.626 h2.16
  text "A. U.L. CODE" at 231.028,5.626 h2.16
  text "E. SUCCESSFUL ELECTRICAL BOARD TEST." at 270.652,2.578 h2.16
  text "E. SUCCESSFUL ELECTRICAL BOARD TEST." at 270.652,2.578 h2.16
  text "B. DATE CODE" at 231.028,2.07 h2.16
  text "B. DATE CODE" at 231.028,2.07 h2.16
  text "C. FLAMMABILITY RATING" at 231.028,-1.486 h2.16
  text "C. FLAMMABILITY RATING" at 231.028,-1.486 h2.16
  text "8. REMOVE THE FLASHS WHICH SMALLER THAN HOLE SIZE." at 223.662,-6.82 h2.16
  text "8. REMOVE THE FLASHS WHICH SMALLER THAN HOLE SIZE." at 223.662,-6.82 h2.16
  text "9. REMOVE ALL SHAPE EDGES AND BURRS .005 MAXIMUM." at 223.662,-11.9 h2.16
  text "9. REMOVE ALL SHAPE EDGES AND BURRS .005 MAXIMUM." at 223.662,-11.9 h2.16
  text "A" at -99.361,-93.208 h3.3
  text "A" at -99.361,-93.208 h3.3
  text "A" at 441.659,-93.208 h3.3
  text "A" at 441.659,-93.208 h3.3
  text "DATA" at 339.652,-100.701 h1.91
  text "UNLESS OTHERWISE SPECIFIED" at 256.061,-100.93 h1.91
  text "SIGNATURES" at 305.007,-101.463 h1.91
  text "ST Microelectronics" at 365.193,-105.544 h5
  text "DRAWN" at 305.007,-106.543 h1.91
  text "YY-MM-DD" at 337.366,-107.051 h1.91
  text "DIMENSIONS ARE IN INCHES" at 256.239,-107.635 h1.91
  text "TOLERANCES ON;" at 256.239,-111.801 h1.91
  text "CHECKED" at 305.007,-112.385 h1.91
  text "YY-MM-DD" at 336.985,-112.385 h1.91
  text "TITLE" at 355.019,-114.62 h1.91
  text "2 PL DECIMALS +" at 256.239,-115.789 h1.91
  text "ENGGRG" at 305.134,-117.084 h1.91
  text "YY-MM-DD" at 337.239,-117.211 h1.91
  text "MB1641C" at 379.853,-119.119 h5
  text "3 PL DECIMALS +" at 256.442,-119.726 h1.91
  text "ISSUED" at 305.007,-122.012 h1.91
  text "ANGLES +" at 256.061,-123.942 h1.91
  text "SIZE   B" at 354.689,-125.72 h1.91
  text "DWG  NO   *******" at 377.219,-125.72 h1.91
  text "REV **" at 423.65,-125.872 h1.91
  text "FRACTIONS +" at 256.061,-127.93 h1.91
  text "SCALE  1:1" at 354.867,-131.613 h1.91
  text "SHEET    1  OF  1" at 404.143,-131.765 h1.91
  text "6" at -48.561,-138.928 h3.3
  text "6" at -48.561,-138.928 h3.3
  text "5" at 40.339,-138.928 h3.3
  text "5" at 40.339,-138.928 h3.3
  text "4" at 129.239,-138.928 h3.3
  text "4" at 129.239,-138.928 h3.3
  text "3" at 218.139,-138.928 h3.3
  text "3" at 218.139,-138.928 h3.3
  text "2" at 307.039,-138.928 h3.3
  text "2" at 307.039,-138.928 h3.3
  text "1" at 395.939,-138.928 h3.3
  text "1" at 395.939,-138.928 h3.3

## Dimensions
6.04,5.5 to 64.46,5.5 on M3-Top Dimensions
11.12,5.5 to 59.38,5.5 on M3-Top Dimensions
1.976,64.936 to 11.12,18.2 on M3-Top Dimensions
1.976,64.936 to 11.12,41.06 on M3-Top Dimensions
1.976,64.936 to 6.04,54.664 on M3-Top Dimensions
9.596,55.131 to 0.25,63.21 on M3-Top Dimensions
6.04,54.664 to 0.25,63.21 on M3-Top Dimensions
70.25,55.336 to 59.38,50.204 on M3-Top Dimensions
70.25,55.336 to 67,54.664 on M3-Top Dimensions
68.126,57.46 to 59.38,5.5 on M3-Top Dimensions
68.126,57.46 to 59.38,27.344 on M3-Top Dimensions
68.126,57.46 to 64.46,51.22 on M3-Top Dimensions
27.122,64.936 to 28.646,63.412 on M2-Board Dimensions
27.122,64.936 to 30.788,57.46 on M2-Board Dimensions
68.126,57.46 to 70.25,55.336 on M2-Board Dimensions
0.25,63.21 to 70.25,55.336 on M2-Board Dimensions
47.424,2.46 to 70.25,4.46 on M2-Board Dimensions
45.423,0.459 to 47.424,2.46 on M2-Board Dimensions
13.751,0.459 to 45.423,0.459 on M2-Board Dimensions
11.75,2.46 to 13.751,0.459 on M2-Board Dimensions
0.25,4.46 to 11.75,2.46 on M2-Board Dimensions
1.976,64.936 to 13.751,0.459 on M2-Board Dimensions
0.25,63.21 to 2.25,2.46 on M2-Board Dimensions
1.976,64.936 to 0.25,63.21 on M2-Board Dimensions
68.126,57.46 to 30.788,57.46 on M2-Board Dimensions
70.25,55.336 to 68.126,57.46 on M2-Board Dimensions
28.646,59.602 to 30.788,57.46 on M2-Board Dimensions
27.122,64.936 to 28.646,63.412 on M2-Board Dimensions
1.976,64.936 to 27.122,64.936 on M2-Board Dimensions
0.25,63.21 to 1.976,64.936 on M2-Board Dimensions
13.751,0.459 to 2.25,2.46 on M2-Board Dimensions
